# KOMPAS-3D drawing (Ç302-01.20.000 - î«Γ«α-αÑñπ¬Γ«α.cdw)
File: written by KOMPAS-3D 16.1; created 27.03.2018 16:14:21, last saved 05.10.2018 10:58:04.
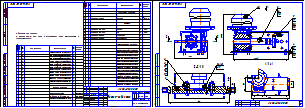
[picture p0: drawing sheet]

Sheets 1-2: A3, landscape

Title block, sheet 1: name: Мотор-редуктор; designation: А302-01.20.000; mass: 28,32; scale: 1:2,5; sheet number: 1; sheets: 2; organisation: ЗАО «Астерион»; sheet format: A3; stored path: Z:\Пресс-формы\РТМ технология\Магна 32\А302-00.20.000 СБ - Мотор-редуктор.cdw; drawn by: Милов; technical control: Лучихин
Title block, sheet 2: sheet number: 2; stored path: Z:\Мембранные насосы\Мембранный электропривод\А302-00.00.000 - ASTRA-302 (МЭ200)\3Д ПВХ\А302-01.20.000 СБ - Мотор-редуктор.cdw

Views: Проекционный вид 2, Местный разрез 1, Разрез А-А
Referenced files in \\192.168.87.28\Konstructor_doc\Мембранные насосы\Мембранный электропривод\А302-00.00.000 - ASTRA-302 (МЭ200)\3Д\: А302-00.20.003 - Ползун.m3d, А302-00.35.001 - Труба 140х140х4.m3d, А302-00.20.004 - Вал.m3d, А302-00.35.002 - Пластина.m3d
Referenced files in \\192.168.87.28\Konstructor_doc\1 ПКИ 3D\Редуктора NMRW\Редукторы\: Редуктор NMRW 063.m3d, Червячный мотор-редуктор NMRV063 АИР80.a3d
Referenced files in \\192.168.87.28\Konstructor_doc\Мембранные насосы\Мембранный электропривод\А302-00.00.000 - ASTRA-302 (МЭ200)\3Д ПВХ\: А302-01.20.001 - Основание.m3d, А302-01.20.001 - Основание.cdw, А302-01.35.000 - Фланец.cdw, А302-01.20.002 - Эксцентрик.cdw, А302-01.35.000 - Фланец.a3d, А302-01.20.002 - Эксцентрик.m3d
Referenced files in C:\Program Files\ASCON\KOMPAS-3D V16\Libs\PartLib\DATA\vault\Methods\Kompas\3D\: PLib_Screw_DIN_7984_1500.m3d, PLib_Washer_1_712.m3d, PLib_Washer_2_712.m3d, PLib_Check_spring_rings_GOST_13942_911.m3d, PLib_Nut_OST92_900.m3d, PLib_Key_prismatic_712.m3d
Referenced files in C:\Program Files\ASCON\KOMPAS-3D V16\Libs\PartLib\DATA\VAULT\Methods\kompas\3d\: PLib_Washer_1_712.m3d, PLib_Washer_2_712.m3d, PLib_Bolt_1_900.m3d
Referenced files in Z:\Мембранные насосы\Мембранный электропривод\А302-00.00.000 - ASTRA-302 (МЭ200)\3Д\: А302-00.20.000 - Мотор-редуктор.a3d, А302-00.20.002 - Эксцентрик.m3d, А302-00.20.003 - Ползун.m3d, А302-00.20.001 - Основание.m3d, А302-00.35.001 - Труба 140х140х4.m3d, А302-00.20.004 - Вал.m3d, А302-00.35.002 - Пластина.m3d
Referenced files: GRAPHIC.TDP
Referenced files in \\192.168.87.28\Konstructor_doc\Мембранные насосы\Мембранный электропривод\А302-00.00.000 - ASTRA-302 (МЭ200)\3Д ПВХ\Отработка\: А302-01.20.000 - Мотор-редуктор.a3d
Referenced files in \\192.168.87.28\Konstructor_doc\1 ПКИ 3D\Двигатели\АИР\: Электродвигатель АИР 80А4 IM 3081 1,1кВт 1400 об..m3d
Referenced files in \\192.168.87.28\Konstructor_doc\1 ПКИ 3D\1 Крепеж стандартный\Подшипник\: Подшипник 52х25х15 62052RSH SKF.m3d
Referenced files in Z:\1 ПКИ 3D\Двигатели\АИР\: Электродвигатель АИР 80А4 IM 3081 1,1кВт 1400 об..m3d
Referenced files in Z:\1 ПКИ 3D\1 Крепеж стандартный\Подшипник\: Подшипник 52х25х15 62052RSH SKF.m3d
Referenced files in Z:\1 ПКИ 3D\Редуктора NMRW\Редукторы\: Редуктор NMRW 063.m3d
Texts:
  Размеры для справок.
  Ползун поз.2, вал поз.3 и эксцентрик поз.5 фиксировать в
  конечной сборке.
  Кольцо A25.65Г ГОСТ 13942-86
  Крепежное изделие ГОСТ
  Кольцо
  ГОСТ
  Сталь 65Г ГОСТ 14959-79
  Шайба C.5.04.019 ГОСТ 11371-78
  Шайба
  Сталь 20 ГОСТ 1050-2013
  Болт М5-6gx35.58.019 ГОСТ 7805-70
  Болт
  Шайба 5 30Х13 019 ГОСТ 6402-70
  Сталь 30Х13 ГОСТ 5632-72
  Гайка М5-6H.5.019 ГОСТ 5915-70
  Гайка
  Шайба C.8.21 ГОСТ 11371-78
  Шайба 8 30Х13 019 ГОСТ 6402-70
  Винт с цилиндрической головкой и
  шестигранным углублением под ключ
  ГОСТ Р ИСО  4762-М8 x 20-6.8-A9J
  Винт с цилиндрической головкой и шестигранным углублением под ключ
  Р ИСО
  Сталь
  Шайба C.8.04.019 ГОСТ 11371-78
  Винт с цилиндрической головкой
  и шестигранным углублением под ключ
  ГОСТ Р ИСО  4762-М8 x 35-A2-70
  Гайка М8-6H.21.12Х18Н10Т ГОСТ 5915-70
  Винт с цилиндрической головкой и шестигранным углублением под ключ ГОСТ Р ИСО  4762-М8 x 35-6.8-A9J
  ГОСТ Р ИСО  4762-М8 x 25-A2-70
  Нержавеющая сталь
  Сталь 12Х18Н10Т ГОСТ 5632-72
  Винт с цилиндрической головкой и шестигранным углублением под ключ ГОСТ Р ИСО  4762-М8 x 25-A2-70
  Шпонка 8 x 7 x 90 ГОСТ 23360-78
  Шпонка
  NMRV063 N P(кВт) V5
  P(мощн./дв.), i(передат. отн.) см. заказ
  Мотор-редуктор / NMRV063 N P(кВт) V5 / P(мощн./дв.), i(передат. отн.) см. заказ
  Двигатель
  Двигатель1400 об/минN=1400/i
  Основание
  Фланец
  @100~)2xA3
  Эксцентрик
  Подшипник 52х25х15 62052RSH SKF
  Подшипник
  RSH
  SKF
  Вал
  Заим.
  Ползун
  Лит-Масса-Масштаб
  Материал-Предприятие
  Title Specification
  Body Specification ( left align )
  Body Specificaton ( centered )
  Поз.
  Кол.
  Приме-
  чание
  Таблица спецификации
  Электродвигатель АИР 80А4 IM 3081 1,1кВт 1400 об.
  Редуктор NMRW 063
  Червячный мотор-редуктор NMRV063 АИР80
  Пластина
  Труба 140х140х4
  Винт с цилиндрической головкой и шестигранным углублением под ключ ГОСТ Р ИСО 4762 - М8 x 25 - A2-70
  Винт с цилиндрической головкой и шестигранным углублением под ключ ГОСТ Р ИСО 4762 - М8 x 35 - A2-70
  Шпонка 8x7x90 ГОСТ 23360-78
Dimensions and other numbers on the sheet: 1; 7; 16; 18; 4; 8; 9; 12; 22; 383,9; 452,1; 5; 14; 20; 58; 65Г; 019; 2; 17; 04; 40Х; 3; 6; 15; 30Х13; 11; 19; 6.8; 10; 21; 13; 12Х18Н10Т; 78; 1400 об/мин; 1:2,5; 28,32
